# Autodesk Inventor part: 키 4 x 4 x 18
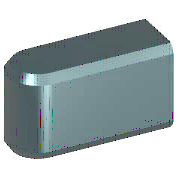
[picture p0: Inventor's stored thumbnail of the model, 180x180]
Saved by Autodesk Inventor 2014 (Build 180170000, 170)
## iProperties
IsCustomPart: 1
Created: 2012-02
Part Number: 키 4 x 4 x 18
Material: 강철, 연강
Description: 키 및 해당 키홈
Document SubType Name: Modeling
Standard: KS B 1311
Designer: mduedu
Standards Organization: KS
Language: ko-KR
Size Designation: 4 x 4 x 18
Categories: <MemberInstance><Categories><Category DisplayName="샤프트 부품" InternalName="7f7aeb1f-a693-4053-b835-cee3144e0d98" Mnemonic="SHFT"><Category DisplayName="키" Interna
Density: 1 g/cm^3
Appearance: Blue - Wall Paint - Glossy
Author: mduedu
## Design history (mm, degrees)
sketch "스케치1"
  geometry: L1 (2, 2)-(18, 2); L2 (18, 2)-(18, -2); L3 (18, -2)-(2, -2); L4 (0, 7)-(0, -7) reference; L5 (-5, 0)-(30, 0) reference; A1 r 2 centre (2, 0) between (2, 2) and (2, -2)
  constraints: 6 end point, 3 tangent, 2 point on circle, 1 centre point, 1 horizontal, 1 parallel, 1 perpendicular, 1 point on line
  dimensions: "d0" = 2 radius of A1 (= 0.5 x PB); "d7" = 18 distance between parallel lines of L2 L4 (= NLG)
extrude "본체1" new body sketch "스케치1" taper "d3" = 0 deg; stored distance "d4" = 10
workaxis "Work Axis1"
workplane "Work Plane4"
body "Solid1"
workplane "Work Plane1"
workplane "Work Plane2"
chamfer "모따기1" distance "d8" = 0.25 (= PHH); stored, may be unused: second distance "d9" = 0.25 (= PHH), angle "d13" = 45 deg
other parameters: "d1" = -2.5 (= -PNT), "d2" = 1.5 (= PH - PNT), "NLG" = 18 [user parameter; used in 2 equation terms], "PB" = 4 [user parameter; used in 1 equation term], "PNT" = 2.5 [user parameter; used in 2 equation terms], "PH" = 4 [user parameter; used in 1 equation term], "PHH" = 0.25 [user parameter; used in 2 equation terms], "d10" = 0, "d16" = 0, "d17" = 0, "d18" = 0, "RR" = 0.08 [user parameter], "WDMAX" = 12 [user parameter], "PLB1" = 18 (= NLG) [user parameter], "PUEB" = 1.8 [user parameter]
